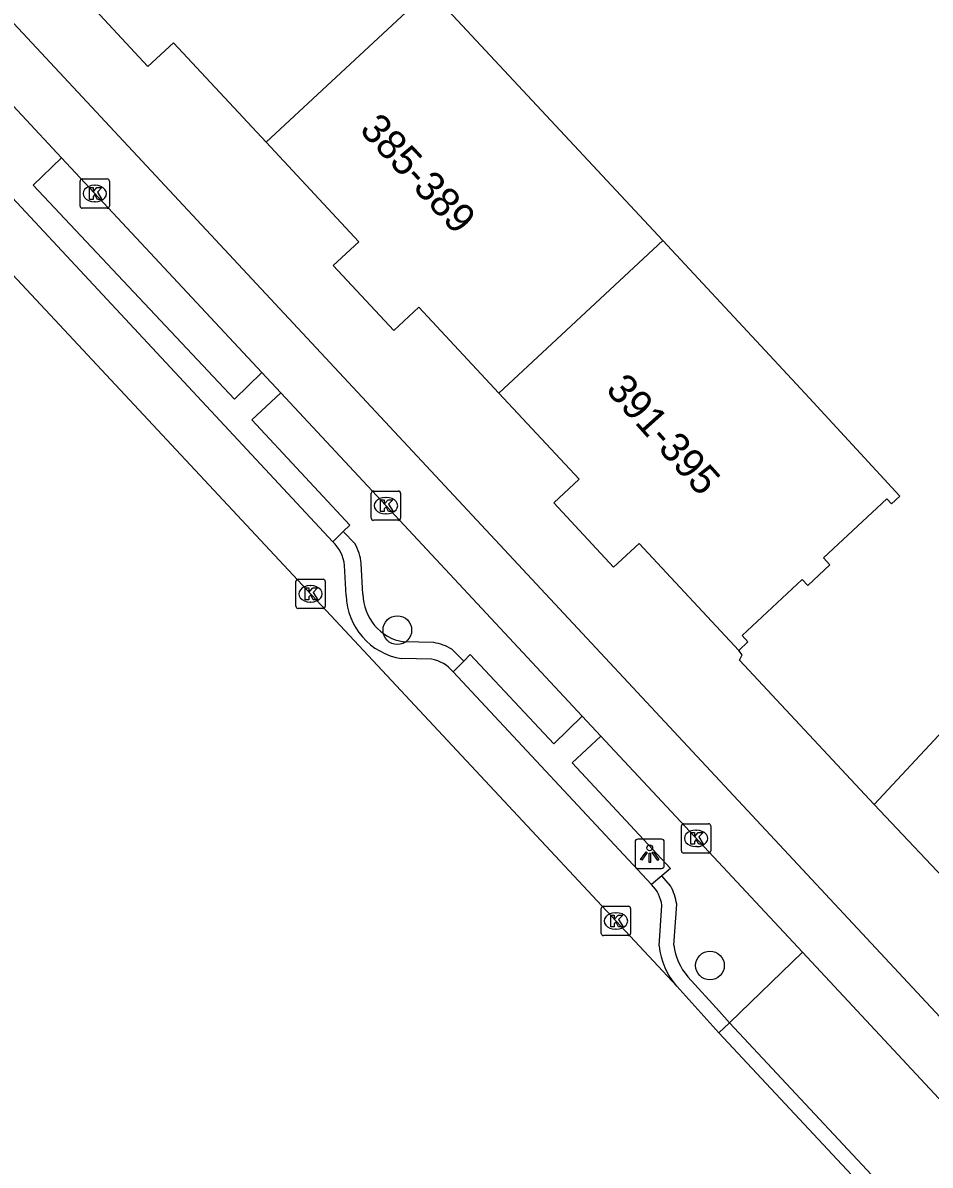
# Model space of a CAD drawing. Extents: x 163150 to 163546, y 380933 to 381635.
# Drawn here: x 163235.55 to 163266.51, y 381108.09 to 381147.06 of the extents above; entities that cross this region are included whole.
import ezdxf

# ---------------------------------------------------------------- set-up
doc = ezdxf.new("R2010")
doc.units = 0
for name, color, linetype in [('IMGEO_Berm_open', 7, 'Continuous'), ('IMGEO_Boom', 7, 'Continuous'), ('IMGEO_Fietspad_gesloten', 7, 'Continuous'), ('IMGEO_Kolk', 7, 'Continuous'), ('IMGEO_Lichtpunt', 7, 'Continuous'), ('IMGEO_Pand', 7, 'Continuous'), ('IMGEO_Pand_nummerreeks', 7, 'Continuous'), ('IMGEO_Parkeervlak_open', 7, 'Continuous'), ('IMGEO_Rijbaan_lokaal_gesloten', 7, 'Continuous'), ('IMGEO_Rijbaan_lokaal_open', 7, 'Continuous'), ('IMGEO_Voetpad_open', 7, 'Continuous')]:
    doc.layers.add(name, color=color, linetype=linetype)

msp = doc.modelspace()

# ---------------------------------------------------------------- linework, layer by layer
at = {"layer": 'IMGEO_Berm_open'}
for points in [[(163246.882, 381129.291), (163246.485, 381129.7)], [(163247.15, 381127.57), (163247.098, 381128.616)], [(163249.571, 381125.913), (163248.547, 381125.938)], [(163250.594, 381125.286), (163250.2, 381125.678), (163250.19, 381125.688)], [(163257.652, 381117.619), (163257.359, 381117.962)], [(163257.764, 381115.595), (163257.863, 381116.99)], [(163259.661, 381112.947), (163259.321, 381113.325), (163258.248, 381114.516)]]:
    msp.add_lwpolyline(points, dxfattribs=at)
for centre, radius, start, end in [((163245.366, 381128.434), 1.742, 6.0075, 29.4818), ((163248.835, 381127.598), 1.685, 180.9684, 260.159), ((163249.289, 381124.172), 1.764, 59.2626, 80.786), ((163256.159, 381116.768), 1.718, 7.4141, 29.6743), ((163259.705, 381115.818), 1.954, 186.5427, 221.7758)]:
    msp.add_arc(centre, radius, start, end, dxfattribs=at)
at = {"layer": 'IMGEO_Boom'}
for centre in [(163248.329, 381126.34), (163258.999, 381114.9)]:
    msp.add_circle(centre, 0.489, dxfattribs=at)
at = {"layer": 'IMGEO_Fietspad_gesloten'}
for points in [[(163306.558, 381070.608), (163278.278, 381100.892), (163188.415, 381197.241)], [(163232.791, 381146.822), (163236.873, 381142.447)], [(163236.873, 381142.447), (163243.701, 381135.131)], [(163243.701, 381135.131), (163244.35, 381134.436)], [(163244.35, 381134.436), (163254.641, 381123.403)], [(163254.641, 381123.403), (163255.277, 381122.722)], [(163255.277, 381122.722), (163262.153, 381115.349)]]:
    msp.add_lwpolyline(points, dxfattribs=at)
at = {"layer": 'IMGEO_Kolk'}
for p, q in [((163237.577, 381141.734), (163238.429, 381141.734)), ((163237.502, 381140.808), (163237.502, 381141.66)), ((163237.99, 381141.514), (163238.015, 381141.514)), ((163238.503, 381141.66), (163238.503, 381140.808)), ((163238.013, 381140.954), (163237.988, 381140.954)), ((163238.429, 381140.734), (163237.577, 381140.734)), ((163247.439, 381130.16), (163247.439, 381131.012)), ((163247.514, 381131.086), (163248.366, 381131.086)), ((163247.927, 381130.866), (163247.952, 381130.866)), ((163248.44, 381131.012), (163248.44, 381130.16)), ((163248.366, 381130.086), (163247.514, 381130.086)), ((163247.95, 381130.306), (163247.925, 381130.306)), ((163244.942, 381128.078), (163245.794, 381128.078)), ((163244.867, 381127.152), (163244.867, 381128.004)), ((163245.355, 381127.858), (163245.38, 381127.858)), ((163245.868, 381128.004), (163245.868, 381127.152)), ((163245.378, 381127.298), (163245.353, 381127.298)), ((163245.794, 381127.078), (163244.942, 381127.078)), ((163258.025, 381118.809), (163258.025, 381119.661)), ((163258.1, 381119.735), (163258.952, 381119.735)), ((163258.513, 381119.515), (163258.538, 381119.515)), ((163259.026, 381119.661), (163259.026, 381118.809)), ((163258.952, 381118.735), (163258.1, 381118.735)), ((163258.536, 381118.955), (163258.511, 381118.955)), ((163255.289, 381115.993), (163255.289, 381116.845)), ((163255.364, 381116.919), (163256.216, 381116.919)), ((163256.29, 381116.845), (163256.29, 381115.993)), ((163255.777, 381116.699), (163255.802, 381116.699)), ((163255.8, 381116.139), (163255.775, 381116.139)), ((163256.216, 381115.919), (163255.364, 381115.919))]:
    msp.add_line(p, q, dxfattribs=at)
for points in [[(163237.577, 381141.734), (163238.429, 381141.734)], [(163237.502, 381140.808), (163237.502, 381141.66)], [(163237.823, 381141.434), (163237.946, 381141.434), (163237.946, 381141.283), (163238.076, 381141.434), (163238.24, 381141.434), (163238.094, 381141.283), (163238.247, 381141.034), (163238.095, 381141.034), (163238.01, 381141.198), (163237.946, 381141.131), (163237.946, 381141.034), (163237.823, 381141.034), (163237.823, 381141.434)], [(163238.503, 381141.66), (163238.503, 381140.808)], [(163238.429, 381140.734), (163237.577, 381140.734)], [(163247.439, 381130.16), (163247.439, 381131.012)], [(163247.514, 381131.086), (163248.366, 381131.086)], [(163247.76, 381130.786), (163247.883, 381130.786), (163247.883, 381130.635), (163248.013, 381130.786), (163248.177, 381130.786), (163248.031, 381130.635), (163248.184, 381130.386), (163248.032, 381130.386), (163247.947, 381130.55), (163247.883, 381130.483), (163247.883, 381130.386), (163247.76, 381130.386), (163247.76, 381130.786)], [(163248.44, 381131.012), (163248.44, 381130.16)], [(163248.366, 381130.086), (163247.514, 381130.086)], [(163244.942, 381128.078), (163245.794, 381128.078)], [(163244.867, 381127.152), (163244.867, 381128.004)], [(163245.188, 381127.778), (163245.311, 381127.778), (163245.311, 381127.627), (163245.441, 381127.778), (163245.605, 381127.778), (163245.459, 381127.627), (163245.612, 381127.378), (163245.46, 381127.378), (163245.375, 381127.542), (163245.311, 381127.475), (163245.311, 381127.378), (163245.188, 381127.378), (163245.188, 381127.778)], [(163245.868, 381128.004), (163245.868, 381127.152)], [(163245.794, 381127.078), (163244.942, 381127.078)], [(163258.025, 381118.809), (163258.025, 381119.661)], [(163258.1, 381119.735), (163258.952, 381119.735)], [(163259.026, 381119.661), (163259.026, 381118.809)], [(163258.346, 381119.435), (163258.469, 381119.435), (163258.469, 381119.284), (163258.599, 381119.435), (163258.763, 381119.435), (163258.617, 381119.284), (163258.77, 381119.035), (163258.618, 381119.035), (163258.533, 381119.199), (163258.469, 381119.132), (163258.469, 381119.035), (163258.346, 381119.035), (163258.346, 381119.435)], [(163258.952, 381118.735), (163258.1, 381118.735)], [(163255.289, 381115.993), (163255.289, 381116.845)], [(163255.364, 381116.919), (163256.216, 381116.919)], [(163256.29, 381116.845), (163256.29, 381115.993)], [(163255.61, 381116.619), (163255.733, 381116.619), (163255.733, 381116.468), (163255.863, 381116.619), (163256.027, 381116.619), (163255.881, 381116.468), (163256.034, 381116.219), (163255.882, 381116.219), (163255.797, 381116.383), (163255.733, 381116.316), (163255.733, 381116.219), (163255.61, 381116.219), (163255.61, 381116.619)], [(163256.216, 381115.919), (163255.364, 381115.919)]]:
    msp.add_lwpolyline(points, dxfattribs=at)
for centre, start, end in [((163237.579, 381141.658), 91.552, 178.448), ((163237.579, 381141.658), 91.552, 178.448), ((163238.427, 381141.658), 1.552, 88.448), ((163238.427, 381141.658), 1.552, 88.448), ((163237.579, 381140.81), 181.552, 268.448), ((163237.579, 381140.81), 181.552, 268.448), ((163238.427, 381140.81), 271.552, 358.448), ((163238.427, 381140.81), 271.552, 358.448), ((163247.516, 381131.01), 91.552, 178.448), ((163247.516, 381131.01), 91.552, 178.448), ((163248.364, 381131.01), 1.552, 88.448), ((163248.364, 381131.01), 1.552, 88.448), ((163247.516, 381130.162), 181.552, 268.448), ((163247.516, 381130.162), 181.552, 268.448), ((163248.364, 381130.162), 271.552, 358.448), ((163248.364, 381130.162), 271.552, 358.448), ((163244.944, 381128.002), 91.552, 178.448), ((163244.944, 381128.002), 91.552, 178.448), ((163245.792, 381128.002), 1.552, 88.448), ((163245.792, 381128.002), 1.552, 88.448), ((163244.944, 381127.154), 181.552, 268.448), ((163244.944, 381127.154), 181.552, 268.448), ((163245.792, 381127.154), 271.552, 358.448), ((163245.792, 381127.154), 271.552, 358.448), ((163258.102, 381119.659), 91.552, 178.448), ((163258.102, 381119.659), 91.552, 178.448), ((163258.95, 381119.659), 1.552, 88.448), ((163258.95, 381119.659), 1.552, 88.448), ((163258.102, 381118.811), 181.552, 268.448), ((163258.102, 381118.811), 181.552, 268.448), ((163258.95, 381118.811), 271.552, 358.448), ((163258.95, 381118.811), 271.552, 358.448), ((163255.366, 381116.843), 91.552, 178.448), ((163255.366, 381116.843), 91.552, 178.448), ((163256.214, 381116.843), 1.552, 88.448), ((163256.214, 381116.843), 1.552, 88.448), ((163255.366, 381115.995), 181.552, 268.448), ((163255.366, 381115.995), 181.552, 268.448), ((163256.214, 381115.995), 271.552, 358.448), ((163256.214, 381115.995), 271.552, 358.448)]:
    msp.add_arc(centre, 0.0765, start, end, dxfattribs=at)
for centre, major_axis, ratio, start_param, end_param in [((163237.989, 381141.234), (-0.387, 0.002), 0.722429, 4.712389, 7.853982), ((163238.014, 381141.234), (-0.39, 0.002), 0.717154, 1.570796, 4.712389), ((163247.926, 381130.586), (-0.387, 0.002), 0.722429, 4.712389, 7.853982), ((163247.951, 381130.586), (-0.39, 0.002), 0.717154, 1.570796, 4.712389), ((163245.354, 381127.578), (-0.387, 0.002), 0.722429, 4.712389, 7.853982), ((163245.379, 381127.578), (-0.39, 0.002), 0.717154, 1.570796, 4.712389), ((163258.512, 381119.235), (-0.387, 0.002), 0.722429, 4.712389, 7.853982), ((163258.537, 381119.235), (-0.39, 0.002), 0.717154, 1.570796, 4.712389), ((163255.776, 381116.419), (-0.387, 0.002), 0.722429, 4.712389, 7.853982), ((163255.801, 381116.419), (-0.39, 0.002), 0.717154, 1.570796, 4.712389)]:
    msp.add_ellipse(centre, major_axis=major_axis, ratio=ratio, start_param=start_param, end_param=end_param, dxfattribs=at)
at = {"layer": 'IMGEO_Lichtpunt'}
for p, q in [((163256.444, 381119.114), (163256.444, 381118.307)), ((163256.444, 381119.114), (163256.444, 381118.307)), ((163257.346, 381119.209), (163256.538, 381119.209)), ((163257.346, 381119.209), (163256.538, 381119.209)), ((163257.44, 381118.307), (163257.44, 381119.114)), ((163257.44, 381118.307), (163257.44, 381119.114)), ((163256.538, 381118.213), (163257.346, 381118.213)), ((163256.538, 381118.213), (163257.346, 381118.213))]:
    msp.add_line(p, q, dxfattribs=at)
for points in [[(163256.818, 381118.778), (163256.857, 381118.75), (163256.669, 381118.488), (163256.631, 381118.515), (163256.818, 381118.778)], [(163256.92, 381118.73), (163256.967, 381118.73), (163256.967, 381118.408), (163256.92, 381118.408), (163256.92, 381118.73)], [(163257.03, 381118.75), (163257.068, 381118.777), (163257.255, 381118.515), (163257.216, 381118.487), (163257.03, 381118.75)]]:
    msp.add_lwpolyline(points, dxfattribs=at)
msp.add_circle((163256.943, 381118.912), 0.0994, dxfattribs=at)
for centre, start, end in [((163256.538, 381119.114), 90, 180), ((163256.538, 381119.114), 90, 180), ((163257.346, 381119.114), 0, 90), ((163257.346, 381119.114), 0, 90), ((163256.538, 381118.307), 180, 270), ((163256.538, 381118.307), 180, 270), ((163257.346, 381118.307), 270, 0), ((163257.346, 381118.307), 270, 360)]:
    msp.add_arc(centre, 0.0946, start, end, dxfattribs=at)
at = {"layer": 'IMGEO_Pand'}
for points in [[(163235.89, 381151.513), (163238.59, 381148.613), (163237.729, 381147.811), (163239.819, 381145.566), (163240.693, 381146.38), (163243.854, 381142.984)], [(163243.854, 381142.984), (163249.431, 381148.176)], [(163257.39, 381139.627), (163249.431, 381148.176)], [(163251.798, 381134.42), (163249.065, 381137.356), (163248.208, 381136.558), (163246.143, 381138.777), (163247.015, 381139.589), (163243.854, 381142.984)], [(163251.798, 381134.42), (163257.39, 381139.627)], [(163259.979, 381125.642), (163260.296, 381125.937), (163260.092, 381126.156), (163262.145, 381128.068), (163262.334, 381127.865), (163263.092, 381128.571), (163262.875, 381128.804), (163265.037, 381130.817), (163265.197, 381130.645), (163265.483, 381130.906), (163262.246, 381134.41), (163257.39, 381139.627)], [(163259.979, 381125.642), (163256.579, 381129.295), (163255.709, 381128.485), (163253.666, 381130.681), (163254.53, 381131.485), (163251.798, 381134.42)]]:
    msp.add_lwpolyline(points, dxfattribs=at)
at = {"layer": 'IMGEO_Parkeervlak_open'}
for points in [[(163246.582, 381127.522), (163246.531, 381128.55)], [(163249.496, 381125.345), (163248.469, 381125.37)], [(163257.261, 381115.567), (163257.359, 381116.952)]]:
    msp.add_lwpolyline(points, dxfattribs=at)
for centre, radius, start, end in [((163245.247, 381128.406), 1.292, 6.4081, 47.0644), ((163248.834, 381127.594), 2.254, 181.8252, 260.6671), ((163249.29, 381124.135), 1.227, 39.8818, 80.3438), ((163256.13, 381116.779), 1.242, 8.0304, 45.1645), ((163259.71, 381115.826), 2.463, 186.0298, 221.3738)]:
    msp.add_arc(centre, radius, start, end, dxfattribs=at)
at = {"layer": 'IMGEO_Rijbaan_lokaal_gesloten'}
for points in [[(163257.862, 381114.198), (163229.126, 381144.967)], [(163259.301, 381112.6), (163257.862, 381114.198)], [(163266.09, 381105.339), (163259.301, 381112.6)]]:
    msp.add_lwpolyline(points, dxfattribs=at)
at = {"layer": 'IMGEO_Rijbaan_lokaal_open'}
for points in [[(163262.153, 381115.349), (163259.661, 381112.947)], [(163262.153, 381115.349), (163268.976, 381108.034)], [(163266.455, 381105.68), (163259.661, 381112.947)]]:
    msp.add_lwpolyline(points, dxfattribs=at)
at = {"layer": 'IMGEO_Voetpad_open'}
for points in [[(163246.127, 381129.352), (163231.174, 381145.393)], [(163243.701, 381135.131), (163242.768, 381134.219), (163235.896, 381141.52), (163236.873, 381142.447)], [(163281.562, 381138.569), (163264.607, 381120.389)], [(163244.35, 381134.436), (163243.361, 381133.518), (163246.711, 381129.919), (163246.485, 381129.7)], [(163246.485, 381129.7), (163246.127, 381129.352)], [(163254.641, 381123.403), (163253.671, 381122.467), (163250.819, 381125.512), (163250.594, 381125.286)], [(163264.607, 381120.389), (163260.011, 381125.316), (163260.093, 381125.495), (163259.979, 381125.642)], [(163250.594, 381125.286), (163250.232, 381124.922)], [(163257.005, 381117.659), (163250.232, 381124.922)], [(163255.277, 381122.722), (163254.299, 381121.813), (163257.652, 381118.213), (163257.359, 381117.962)], [(163264.607, 381120.389), (163267.528, 381117.294)], [(163257.359, 381117.962), (163257.005, 381117.659)], [(163259.661, 381112.947), (163259.301, 381112.6)]]:
    msp.add_lwpolyline(points, dxfattribs=at)

# ---------------------------------------------------------------- texts
at = {"layer": 'IMGEO_Pand_nummerreeks'}
for s, rotation, p in [('385-389', 312.9904, (163247.007, 381143.379)), ('391-395', 311.8337, (163255.411, 381134.521))]:
    msp.add_text(s, height=1, rotation=rotation, dxfattribs=at).set_placement(p)

doc.saveas('drawing.dxf')
